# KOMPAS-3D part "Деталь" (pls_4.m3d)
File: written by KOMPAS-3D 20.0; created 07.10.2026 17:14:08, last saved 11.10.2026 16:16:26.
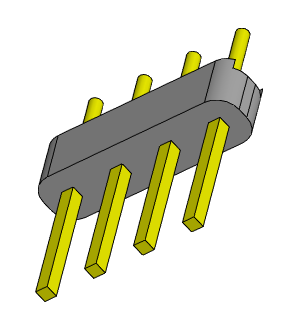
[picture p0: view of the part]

Document properties: Полное имя файла: D:\myProjects\Progect_esp32\box_compas\разъемы\pls_4.m3d

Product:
- Part/product: Деталь
    Масса: 0.000505328
  - Body: Тело 1
      Масса: 0.000521406

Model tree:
1. Эскиз:1
2. Элемент выдавливания:1
     Расстояние 1 = 2.5
3. Эскиз:2  (with: Элемент выдавливания:1)
4. Элемент выдавливания:2
     Расстояние 1 = 6
5. Массив по сетке:1  (with: Элемент выдавливания:2, Эскиз:2)  (4 pattern instances)
     Шаг 1 = 2.54; Угол раствора = 90
6. Эскиз:3  (with: Элемент выдавливания:1)
7. Элемент выдавливания:3
     Расстояние 1 = 3
8. Массив по сетке:2  (with: Элемент выдавливания:3, Эскиз:3)  (4 pattern instances)
     Шаг 1 = 2.54; Угол раствора = 90; Геометрический массив = 128
9. Эскиз:4  (with: Элемент выдавливания:1)
10. Элемент выдавливания:4
     Расстояние 2 = 10.16
11. Элемент выдавливания:5
     Расстояние 1 = 3
12. Скругление:1  (with: Элемент выдавливания:1)
     Радиус = 1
